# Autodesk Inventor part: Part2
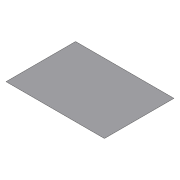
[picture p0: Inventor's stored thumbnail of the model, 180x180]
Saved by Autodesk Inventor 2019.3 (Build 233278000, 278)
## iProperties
Created: 2019-01
Part Number: Part2
Material: Generic
Document SubType Name: Modeling
Designer: m.vorobev
Density: 1 g/cm^3
Appearance: Default
Author: m.vorobev
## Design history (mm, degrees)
sketch "Sketch1"
  geometry: L1 (359.035, 253.684)-(-359.035, 253.684); L2 (-359.035, 253.684)-(-359.035, -253.684); L3 (-359.035, -253.684)-(359.035, -253.684); L4 (359.035, -253.684)-(359.035, 253.684); L5 (359.035, 253.684)-(-359.035, -253.684); L6 (-359.035, 253.684)-(359.035, -253.684); L7 (-359.035, 253.684)-(359.035, 253.684); L8 (359.035, 253.684)-(359.035, -253.684); L9 (359.035, -253.684)-(-359.035, -253.684); L10 (-359.035, -253.684)-(-359.035, 253.684); 1 further point; 1 other entity
  constraints: 12 end point, 2 midpoint, 2 parallel, 1 horizontal, 1 perpendicular, 1 vertical, 2 other
  dimensions: "d1" = 718.069 distance of L3.end L9.end (derived); "d7" = 507.368 distance of L7.end L3.end (derived)
  node "Image1"
extrude "Extrusion1" new body sketch "Sketch1" distance "d17" = 0.1; taper "d18" = 0 deg
feature "Decal1"
body "Solid1"
